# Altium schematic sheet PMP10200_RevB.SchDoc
size 431 x 279 mm; Date: Not shown in title block; ApprovedBy: Not shown in title block; CheckedBy: Not shown in title block; Author: Not shown in title block; CompanyName: Not shown in title block; Engineer: Not shown in title block; Organization: Not shown in title block; Address1: Not shown in title block; Address2: Not shown in title block; Address3: Not shown in title block; Address4: Not shown in title block; DocumentNumber: 1; Revision: Use project parameter SCH_Rev; SheetNumber: 1; SheetTotal: 1; PageSetup: Record=PageOptions¦CenterHorizontal=True¦CenterVertical=True¦PrintScale=1.00¦XCorrection=1.00¦YCorrection=1.00¦PrintKind=0¦BorderSize=5000000¦LeftOffset=0¦BottomOffset=0¦Orientation=2¦PaperLength=1000¦PaperWidth=1000¦Scale=100¦PaperSource=15¦PrintQuality=600¦MediaType=1¦DitherType=10¦PaperKind=Letter¦PrintScaleMode=1
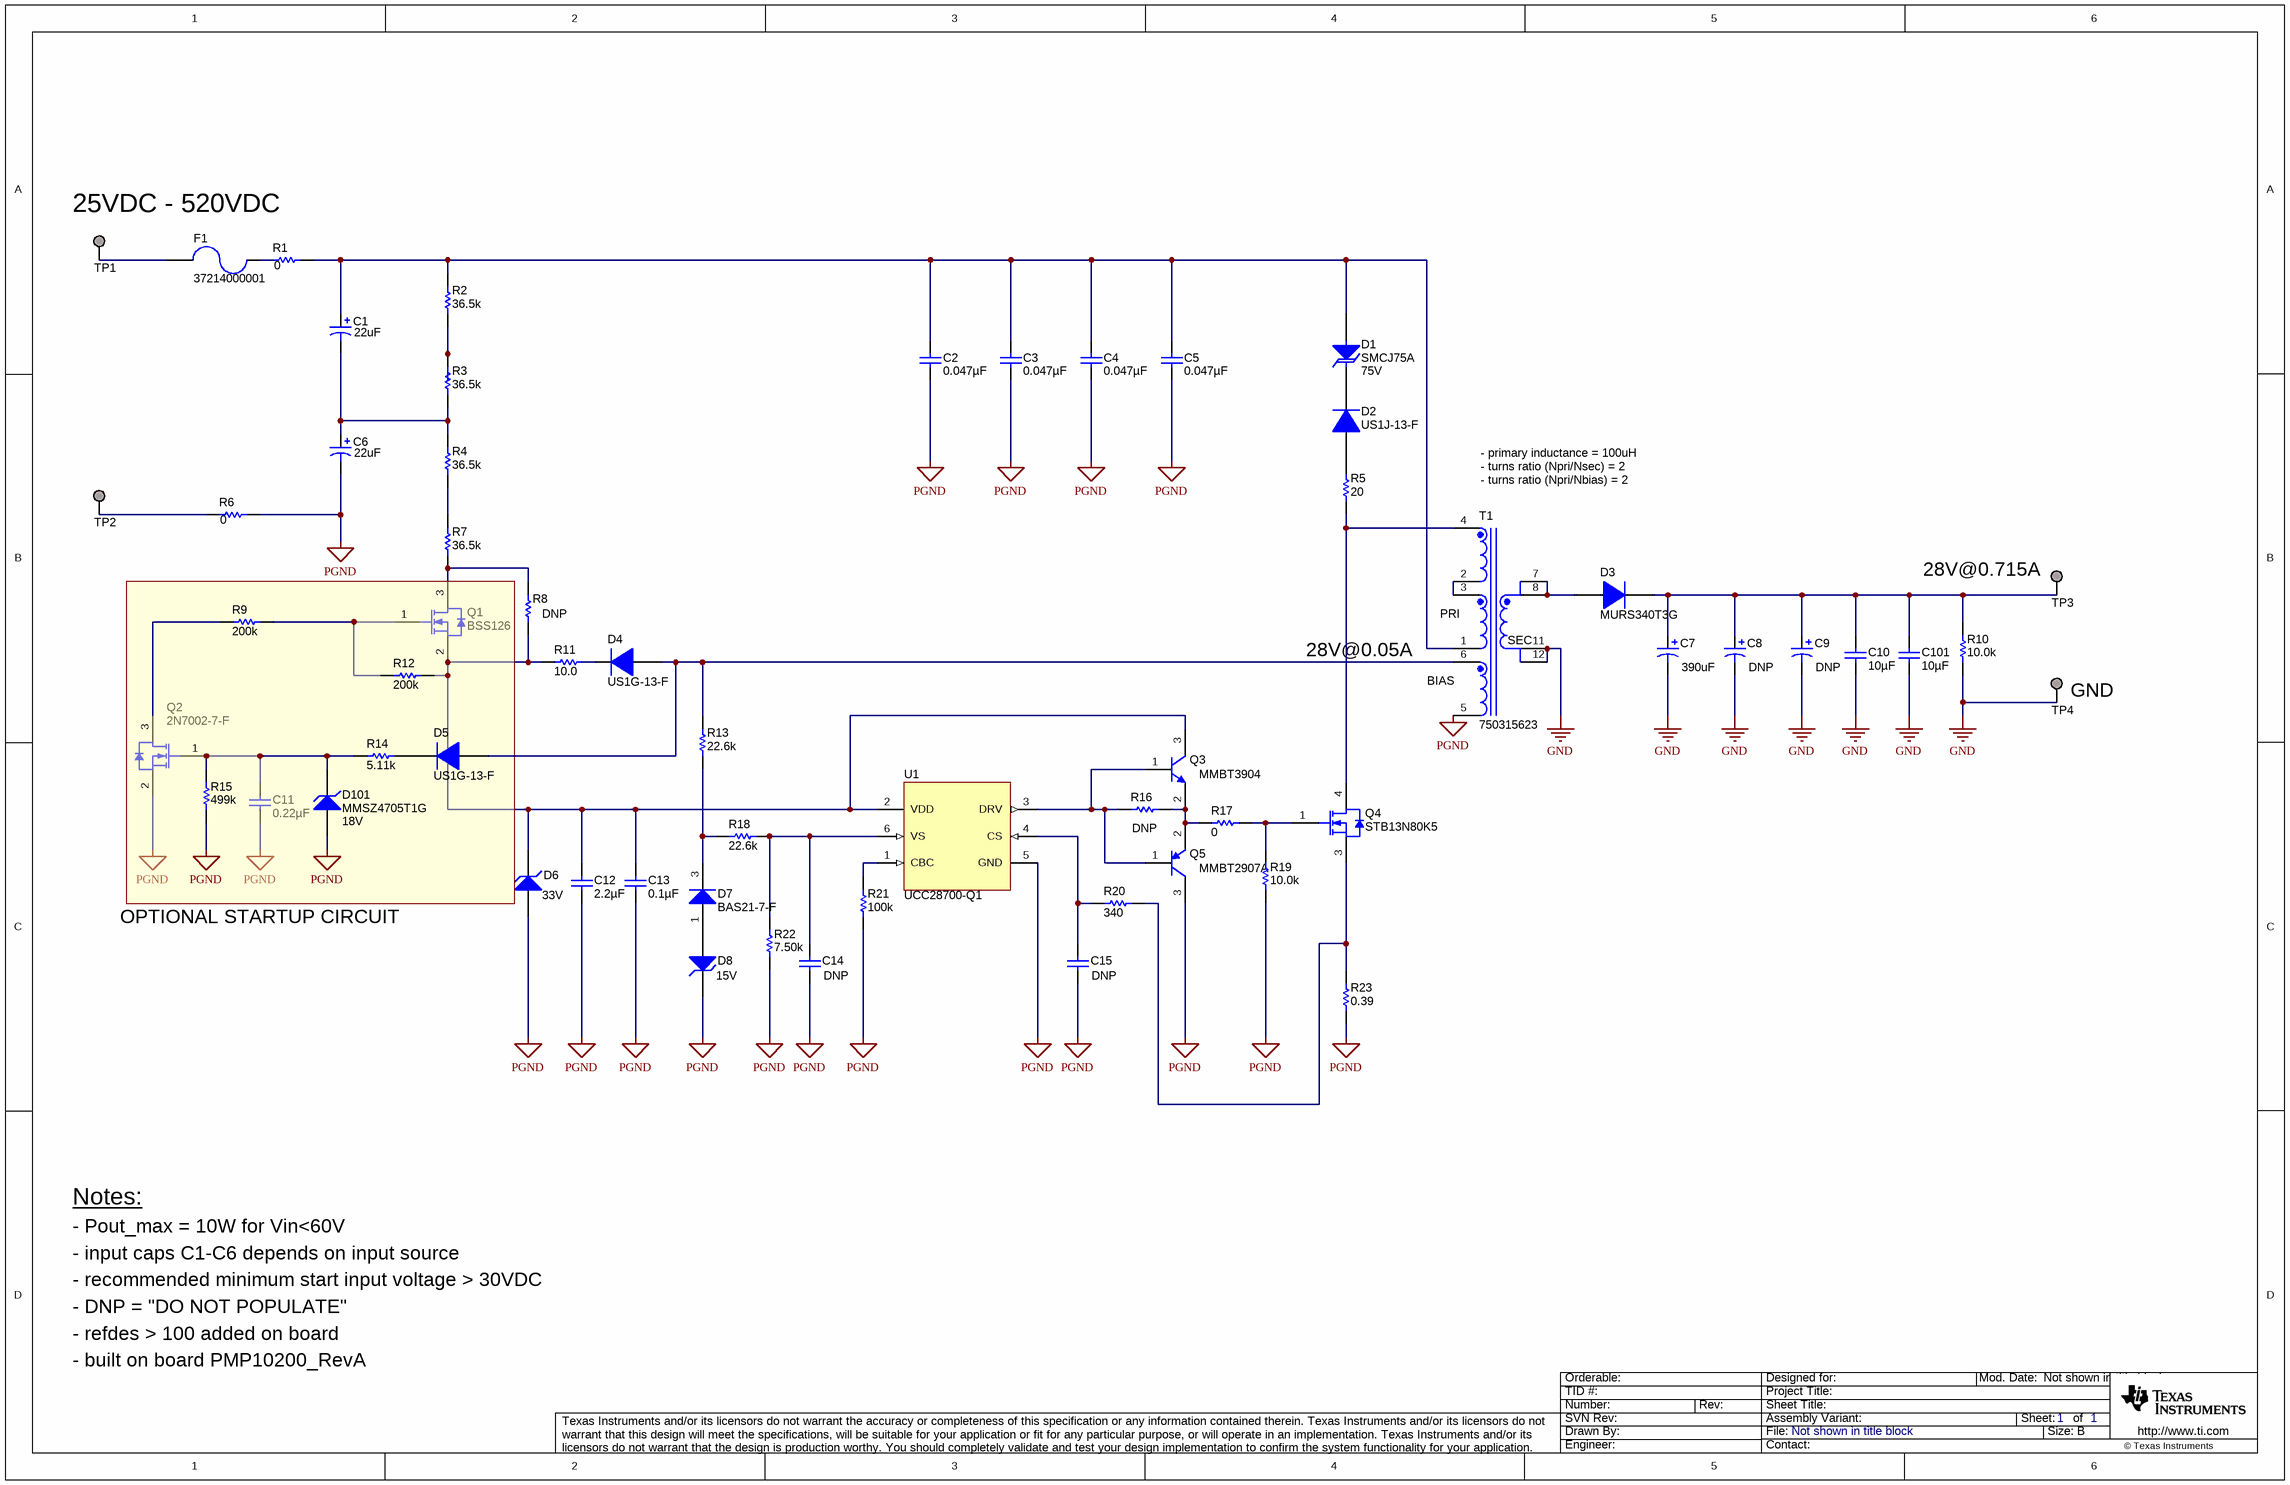
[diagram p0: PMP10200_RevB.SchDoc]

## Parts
C1  value 22uF  [EE_1800x2500]  (hidden comment: EKXG401ELL220)
C2  ValueDisplayed: 0.047µF  [1210]  (hidden comment: GRM32DR72J473KW01L)
C3  ValueDisplayed: 0.047µF  [1210]  (hidden comment: GRM32DR72J473KW01L)
C4  ValueDisplayed: 0.047µF  [1210]  (hidden comment: GRM32DR72J473KW01L)
C5  ValueDisplayed: 0.047µF  [1210]  (hidden comment: GRM32DR72J473KW01L)
C6  value 22uF  [EE_1800x2500]  (hidden comment: EKXG401ELL220)
C7  value 390uF  [SM_RADIAL_J16]  (hidden comment: EEVFK1H391)
C8  DNP  [SM_RADIAL_J16]
C9  value DNP  [SM_RADIAL_J16]  (hidden comment: EEV-FK1H102M)
C10  ValueDisplayed: 10µF  [1210]  (hidden comment: GRM32ER71H106KA12L)
C11  ValueDisplayed: 0.22µF  [0805_HV]  (hidden comment: GRM21BR71H224KA01L)
C12  ValueDisplayed: 2.2µF  [1206_190]  (hidden comment: GCM31CR71H225KA55L)
C13  ValueDisplayed: 0.1µF  [0603]  (hidden comment: C1608X7R1H104K)
C14  DNP  [0603]
C15  DNP  [0603]
C101  ValueDisplayed: 10µF  [1210]  (hidden comment: GRM32ER71H106KA12L)
D1  SMCJ75A  value 75V  [SMC]
D2  US1J-13-F  [SMA]
D3  MURS340T3G  [SMC]
D4  US1G-13-F  [SMA]
D5  US1G-13-F  [SMA]
D6  value 33V  [SOD-123]  (hidden comment: MMSZ5257B-7-F)
D7  BAS21-7-F  [SOT-23]
D8  value 15V  [SMA]  (hidden comment: SMAZ15)
D101  MMSZ4705T1G  value 18V  [SOD-123]
F1  37214000001  [FUSE_372]
Q1  BSS126  [SOT-23]
Q2  2N7002-7-F  [SOT-23]
Q3  MMBT3904  [SOT-23]
Q4  STB13N80K5  [DDPAK]
Q5  MMBT2907A  [SOT-23]
R1  value 0  [1210]  (hidden comment: Used in BOM report)
R2  ValueDisplayed: 36.5k  [1206]  (hidden comment: CRCW120636K5FKEA)
R3  ValueDisplayed: 36.5k  [1206]  (hidden comment: CRCW120636K5FKEA)
R4  ValueDisplayed: 36.5k  [1206]  (hidden comment: CRCW120636K5FKEA)
R5  ValueDisplayed: 20  [2010]  (hidden comment: CRCW201020R0JNEF)
R6  value 0  [1210]  (hidden comment: Used in BOM report)
R7  ValueDisplayed: 36.5k  [1206]  (hidden comment: CRCW120636K5FKEA)
R8  DNP  [0805]
R9  ValueDisplayed: 200k  [0603]  (hidden comment: CRCW0603200KJNEA)
R10  ValueDisplayed: 10.0k  [0805_HV]  (hidden comment: CRCW080510K0FKEA)
R11  ValueDisplayed: 10.0  [0805_HV]  (hidden comment: RC0805FR-0710RL)
R12  ValueDisplayed: 200k  [0603]  (hidden comment: CRCW0603200KJNEA)
R13  ValueDisplayed: 22.6k  [0603]  (hidden comment: CRCW060322K6FKEA)
R14  ValueDisplayed: 5.11k  [0805_HV]  (hidden comment: CRCW08055K11FKEA)
R15  ValueDisplayed: 499k  [0603]  (hidden comment: CRCW0603499KFKEA)
R16  DNP  [0805_HV]
R17  ValueDisplayed: 0  [0805_HV]  (hidden comment: CRCW08050000Z0EA)
R18  ValueDisplayed: 22.6k  [0603]  (hidden comment: CRCW060322K6FKEA)
R19  ValueDisplayed: 10.0k  [0805_HV]  (hidden comment: CRCW080510K0FKEA)
R20  ValueDisplayed: 340  [0603]  (hidden comment: CRCW0603340RFKEA)
R21  ValueDisplayed: 100k  [0603]  (hidden comment: CRCW0603100KFKEA)
R22  ValueDisplayed: 7.50k  [0603]  (hidden comment: CRCW06037K50FKEA)
R23  ValueDisplayed: 0.39  [1206]  (hidden comment: ERJ-8RQFR39V)
T1  750315623  [Wurth_750315623]
TP1  Suggest using a net name here  [Keystone1503-2]  (value not drawn)
TP2  Suggest using a net name here  [Keystone1503-2]  (value not drawn)
TP3  Suggest using a net name here  [Keystone1503-2]  (value not drawn)
TP4  Suggest using a net name here  [Keystone1503-2]  (value not drawn)
U1  UCC28700-Q1  [DBV0006A_N]

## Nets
GND: C7.2(-) C8.2(-) C9.2(-) C10.2 C101.2 R10.1 T1.11 T1.12 TP4.1
PGND: C2.2 C3.2 C4.2 C5.2 C6.2(-) C11.2 C12.2 C13.2 C14.2 C15.2 D6.2(A) D8.1(K) D101.2(A) Q2.2(S) Q5.3(C) R6.2 R15.1 R19.1 R21.1 R22.1 R23.1 T1.5 U1.5(GND)
NetC1_1: C1.1(+) C2.1 C3.1 C4.1 C5.1 D1.2(A) R1.2 R2.2 T1.1
NetC1_2: C1.2(-) C6.1(+) R3.1 R4.2
NetC7_1: C7.1(+) C8.1(+) C9.1(+) C10.1 C101.1 D3.1(K) R10.2 TP3.1
NetC11_1: C11.1 D101.1(K) Q2.1(G) R14.2 R15.2
NetC12_1: C12.1 C13.1 D6.1(K) Q1.2(S) Q3.3(C) R8.1 R11.1 R12.2 U1.2(VDD)
NetC14_1: C14.1 R18.1 R22.2 U1.6(VS)
NetC15_1: C15.1 R20.1 U1.4(CS)
NetD1_1: D1.1(K) D2.1(K)
NetD2_2: D2.2(A) R5.2
NetD3_2: D3.2(A) T1.7 T1.8
NetD4_1: D4.1(K) R11.2
NetD4_2: D4.2(A) D5.2(A) R13.1 T1.6
NetD5_1: D5.1(K) R14.1
NetD7_1: D7.1(A) D8.2(A)
NetD7_3: D7.3(K) R13.2 R18.2
NetF1_1: F1.1 R1.1
NetF1_2: F1.2 TP1.1
NetQ1_1: Q1.1(G) R9.2 R12.1
NetQ1_3: Q1.3(D) R7.1 R8.2
NetQ2_3: Q2.3(D) R9.1
NetQ3_1: Q3.1(B) Q5.1(B) R16.1 U1.3(DRV)
NetQ3_2: Q3.2(E) Q5.2(E) R16.2 R17.1
NetQ4_1: Q4.1(G) R17.2 R19.2
NetQ4_3: Q4.3(S) R20.2 R23.2
NetQ4_4: Q4.4(D) R5.1 T1.4
NetR2_1: R2.1 R3.2
NetR4_1: R4.1 R7.2
NetR6_1: R6.1 TP2.1
NetR21_2: R21.2 U1.1(CBC)
NetT1_2: T1.2 T1.3

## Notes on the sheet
- 25VDC - 520VDC
- - primary inductance = 100uH
- - turns ratio (Npri/Nsec) = 2
- (near T1) - turns ratio (Npri/Nbias) = 2
- (near T1) PRI
- 28V@0.715A
- 28V@0.05A
- (near T1) BIAS
- (near T1) SEC
- (near TP4) GND
- OPTIONAL STARTUP CIRCUIT
- - Pout_max = 10W for Vin<60V
- Notes:
- - recommended minimum start input voltage > 30VDC
- - input caps C1-C6 depends on input source
- - DNP = "DO NOT POPULATE"
- - refdes > 100 added on board
- - built on board PMP10200_RevA

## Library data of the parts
C1 = EEU-EE2G680: CAP, AL; Manufacturer: Panasonic; Polarized: Y; CompType: Capacitor; U/M: EA; Cap_F: 0.000068; Tolerance_%: 20; Value1: Unknown; VDC_V: 400; Value2: 400V; IRMS_A: 1.49; TaMin_C: -25; TaMax_C: 105; Cap_Case: 18x25mm; Lifetime @ Temp.: 10000 Hrs @ 105°C; Ripple Current: 1.8A
C2-C5 = GRM32DR72J473KW01L: CAP, CERM, 0.047 µF, 630 V, +/- 10%, X7R, 1210; Manufacturer: MuRata; Polarized: N; CompType: Capacitor; Value: 0.047uF; U/M: EA; Cap_F: 0.000000047; Tolerance_%: 10; Value1: Unknown; VDC_V: 630; Value2: 630V; TaMin_C: -55; TaMax_C: 125
C6 = EEU-EE2G680: CAP, AL; Manufacturer: Panasonic; Polarized: Y; CompType: Capacitor; ValueDisplayed: 22µF; U/M: EA; Cap_F: 0.000068; Tolerance_%: 20; Value1: Unknown; VDC_V: 400; Value2: 400V; IRMS_A: 1.49; TaMin_C: -25; TaMax_C: 105; Cap_Case: 18x25mm; Lifetime @ Temp.: 10000 Hrs @ 105°C; Ripple Current: 1.8A
C7 = EEV-FK1H102M: CAP, AL, 1000 µF, 50 V, +/- 20%, 0.073 ohm, SMD; Manufacturer: Panasonic; Polarized: Y; CompType: Capacitor; U/M: EA; Cap_F: 0.001; Tolerance_%: 20; VDC_V: 50; Value2: 50V; ESR_ohm: 0.073; IRMS_A: 1.61; TaMin_C: -55; TaMax_C: 105; Cap_Case: J16
C8 C9 = EEV-FK1H102M: CAP, AL, 1000 µF, 50 V, +/- 20%, 0.073 ohm, SMD; Manufacturer: Panasonic; Polarized: Y; CompType: Capacitor; ValueDisplayed: 1000µF; U/M: EA; Cap_F: 0.001; Tolerance_%: 20; VDC_V: 50; Value2: 50V; ESR_ohm: 0.073; IRMS_A: 1.61; TaMin_C: -55; TaMax_C: 105; Cap_Case: J16
C10 C101 = GRM32ER71H106KA12L: CAP, CERM, 10 µF, 50 V, +/- 10%, X7R, 1210; Manufacturer: MuRata; Polarized: N; CompType: Capacitor; Value: 10uF; U/M: EA; Cap_F: 0.00001; Tolerance_%: 10; Value1: Unknown; VDC_V: 50; Value2: 50V; TaMin_C: -55; TaMax_C: 125
C11 = GRM21BR71H224KA01L: CAP, CERM, 0.22 µF, 50 V, +/- 10%, X7R, 0805; Manufacturer: MuRata; Polarized: N; CompType: Capacitor; Value: 0.22uF; U/M: EA; Cap_F: 0.00000022; Tolerance_%: 10; Value1: Unknown; VDC_V: 50; Value2: 50V; TaMin_C: -55; TaMax_C: 125; Cap_Case: 0805
C12 = GCM31CR71H225KA55L: CAP, CERM, 2.2 µF, 50 V, +/- 10%, X7R, 1206_190; Manufacturer: MuRata; Polarized: N; CompType: Capacitor; Value: 2.2uF; U/M: EA; Cap_F: 0.0000022; Tolerance_%: 10; Value1: Unknown; VDC_V: 50; Value2: 50V; TaMin_C: -55; TaMax_C: 125; Cap_Case: 1206
C13 = C1608X7R1H104K: CAP, CERM, 0.1 µF, 50 V, +/- 10%, X7R, 0603; Manufacturer: TDK; Polarized: N; CompType: Capacitor; Value: 0.1uF; U/M: EA; Cap_F: 0.0000001; Tolerance_%: 10; ESR_ohm: 0.017; Value1: 0.017 ohm; VDC_V: 50; Value2: 50V; TaMin_C: -55; TaMax_C: 125
C14 C15 = Capacitor: CAP, CERM, xxxF, xxV, [TempCo], xx%, [PackageReference]; Manufacturer: Used in BOM report; Polarized: N; U/M: EA
D1 = SMCJ75A: Diode, TVS, Uni, 75 V, 1500 W, SMC; Manufacturer: Fairchild Semiconductor; U/M: EA; Power_W: 1500; Vr_V: 75; Value1: 1500W
D2 = US1J-13-F: Diode, Ultrafast, 600 V, 1 A, SMA; Manufacturer: Diodes Inc.; U/M: EA; Vf_V: 1.7; Value: 600V; Value1: 1A; Value2: 1.7V; Io_A: 1; Vr_V: 600; TJmax_C: 150
D3 = MURS340T3G: Diode, Ultrafast, 400 V, 3 A, SMC; Manufacturer: ON Semiconductor; U/M: EA; Vf_V: 1.25; Value: 400V; Value1: 3A; Value2: 1.25V; Io_A: 3; Vr_V: 400; TJmax_C: 175; RJC_CperW: 11
D4 D5 = US1G-13-F: Diode, Ultrafast, 400 V, 1 A, SMA; Manufacturer: Diodes Inc.; U/M: EA; Vf_V: 1.3; Value: 400V; Value1: 1A; Value2: 1.3V; Io_A: 1; Vr_V: 400; TJmax_C: 150
D6 = MMSZ5257B-7-F: Diode, Zener, 33 V, 500 mW, SOD-123; Manufacturer: Diodes Inc.; SymbolCreator: a0412235; U/M: EA; Power_W: 0.5; Vz_V: 33; Value1: 0.5W; RJA_CperW: 350
D7 = BAS21-7-F: Diode, Switching, 200 V, 0.2 A, SOT-23; Manufacturer: Diodes Inc.; U/M: EA; Vf_V: 1.25; Value: 200V; Value1: 0.2A; Value2: 1.25V; Io_A: 0.2; Vr_V: 200; TJmax_C: 150; RJC_CperW: 500
D8 = BZG03C15G: Diode, Zener, 15 V, SMA; Manufacturer: ON Semiconductor; SymbolCreator: a0412235; U/M: EA; Power_W: 1.5; Vz_V: 15; Value1: 1.5W; Tolerance_%: ±5%; Power - Max: 1W; Impedance (Max) (Zzt): 10 Ohm; Current - Reverse Leakage @ Vr: 1µA @ 11.4V
D101 = MMSZ4705T1G: Diode, Zener, 18 V, 500 mW, SOD-123; Manufacturer: ON Semiconductor; SymbolCreator: a0412235; U/M: EA; Power_W: 0.5; Vz_V: 18; Value1: 0.5W; RJA_CperW: 340
F1 = 37214000001: Fuse, 4 A, 250 V, TH; Manufacturer: Littelfuse; U/M: EA; OpeningTime_200%_max: 2; VDC_V: 250; Irating_A: 4; Vdrop: 0.075; Soldering_Wave_MaxTemp_C: 260; Soldering_Wave_MaxTime_s: 5
Q1 = BSS126 H6906: MOSFET, N-CH, 600 V, 0.021 A, SOT-23; Manufacturer: Infineon Technologies; Alternate Manufacturer: None; U/M: EA; ChType: N; Value: 600V; VdsMax_V: 600; Value1: ? ohm; Value2: 1.4 nC; QgTyp_nC: 1.4; Vgs_V: 20; IdsMax_A: 0.021
Q2 = 2N7002-7-F: MOSFET, N-CH, 60 V, 0.17 A, SOT-23; Manufacturer: Diodes Inc.; Alternate Manufacturer: None; U/M: EA; ChType: N; Value: 60V; VdsMax_V: 60; Value1: 7.5 ohm; Rdson45_ohm: 7.5; Value2: 223 nC; QgTyp_nC: 223; Vgs_V: 20; IdsMax_A: 0.17
Q3 = MMBT3904, Fairchild Semiconductor: Transistor, NPN, 40 V, 0.2 A, SOT-23; CompType: BJT; PNP: 0; NPN: 1; Vceo_V: 40; Vcesat1_V: 0.2; Value1: 0.2 A; HfeMax: 300; TaMin_C: -55; TaMax_C: 150; U/M: EA
Q4 = STB11N65M5: MOSFET, N-CH, 800 V, DDPAK; Manufacturer: STMicroelectronics; Alternate Manufacturer: None; U/M: EA; ChType: N; Value: 800V; VdsMax_V: 710; Value1: ? ohm; Value2: 17 nC; QgTyp_nC: 17; Vgs_V: 25; IdsMax_A: 9; FET Type: MOSFET N-Channel, Metal Oxide; FET Feature: Standard; Current - Continuous Drain (Id) @ 25°C: 12A (Tc); Rds On (Max) @ Id, Vgs: 450 mOhm @ 6A, 10V; Vgs(th) (Max) @ Id: 5V @ 100µA; Gate Charge (Qg) @ Vgs: 29nC @ 10V; Input Capacitance (Ciss) @ Vds: 870pF @ 100V; Power - Max: 190W
Q5 = MMBT2907A, Fairchild Semiconductor: Transistor, PNP, 60 V, 0.8 A, SOT-23; CompType: BJT; PNP: 1; NPN: 0; Vceo_V: 60; Vcesat1_V: 1.6; IcRated_A: 0.8; Value1: 0.8 A; HfeMax: 300; TaMin_C: -55; TaMax_C: 150; U/M: EA
R1 R6 = Resistor: RES, xxx ohm, x%, xW, [PackageReference]; U/M: EA
R2-R4 R7 = CRCW120636K5FKEA: RES, 36.5 k, 1%, 0.25 W, 1206; Manufacturer: Vishay-Dale; CompType: Resistor; Value: 36.5k; Res_ohm: 36500; Value_Code: 36k5; Tolerance_%: 1; Power_W: 0.25; Value2: 0.25W; VDC_V: 200; TempCo: 100 ppm/C; EIA_Code: E96; U/M: EA
R5 = CRCW201020R0JNEF: RES, 20, 5%, 0.75 W, 2010; Manufacturer: Vishay-Dale; CompType: Resistor; Value: 20; Value_Code: 20R0; Tolerance_%: 5; Power_W: 0.75; Value2: 0.75W; VDC_V: 400; TempCo: 200 ppm/C; EIA_Code: E24; U/M: EA
R8 = Resistor: RES, xxx ohm, x%, xW, [PackageReference]; Manufacturer: Used in BOM report; U/M: EA
R9 R12 = CRCW0603200KJNEA: RES, 200 k, 5%, 0.1 W, 0603; Manufacturer: Vishay-Dale; CompType: Resistor; Value: 200k; Res_ohm: 200000; Tolerance_%: 5; Power_W: 0.1; Value2: 0.1W; VDC_V: 75; TempCo: 200 ppm/C; EIA_Code: E24; U/M: EA
R10 R19 = CRCW080510K0FKEA: RES, 10.0 k, 1%, 0.125 W, 0805; Manufacturer: Vishay-Dale; CompType: Resistor; Value: 10.0k; Res_ohm: 10000; Value_Code: 10k0; Tolerance_%: 1; Power_W: 0.125; Value2: 0.125W; VDC_V: 150; TempCo: 100 ppm/C; EIA_Code: E96; U/M: EA
R11 = RC0805FR-0710RL: RES, 10.0, 1%, 0.125 W, 0805; Manufacturer: Yageo America; CompType: Resistor; Value: 10.0; Res_ohm: 10; Value_Code: 10R0; Tolerance_%: 1; Power_W: 0.125; Value2: 0.125W; VDC_V: 150; TempCo: 200 ppm/C; EIA_Code: E96; U/M: EA
R13 R18 = CRCW060322K6FKEA: RES, 22.6 k, 1%, 0.1 W, 0603; Manufacturer: Vishay-Dale; CompType: Resistor; Value: 22.6k; Res_ohm: 22600; Value_Code: 22k6; Tolerance_%: 1; Power_W: 0.1; Value2: 0.1W; VDC_V: 75; TempCo: 100 ppm/C; EIA_Code: E96; U/M: EA
R14 = CRCW08055K11FKEA: RES, 5.11 k, 1%, 0.125 W, 0805; Manufacturer: Vishay-Dale; CompType: Resistor; Value: 5.11k; Res_ohm: 5110; Value_Code: 5k11; Tolerance_%: 1; Power_W: 0.125; Value2: 0.125W; VDC_V: 150; TempCo: 100 ppm/C; EIA_Code: E96; U/M: EA
R15 = CRCW0603499KFKEA: RES, 499 k, 1%, 0.1 W, 0603; Manufacturer: Vishay-Dale; CompType: Resistor; Value: 499k; Res_ohm: 499000; Tolerance_%: 1; Power_W: 0.1; Value2: 0.1W; VDC_V: 75; TempCo: 100 ppm/C; EIA_Code: E96; U/M: EA
R16 = CRCW08050000Z0EA: RES, 0, 5%, 0.125 W, 0805; Manufacturer: Vishay-Dale; CompType: Resistor; Res_ohm: 0; Value_Code: 0000; Tolerance_%: 5; Power_W: 0.125; Value2: 0.125W; VDC_V: 150; TempCo: 200 ppm/C; EIA_Code: E24; U/M: EA
R17 = CRCW08050000Z0EA: RES, 0, 5%, 0.125 W, 0805; Manufacturer: Vishay-Dale; CompType: Resistor; Value: 0; Value_Code: 0000; Tolerance_%: 5; Power_W: 0.125; Value2: 0.125W; VDC_V: 150; TempCo: 200 ppm/C; EIA_Code: E24; U/M: EA
R20 = CRCW0603340RFKEA: RES, 340, 1%, 0.1 W, 0603; Manufacturer: Vishay-Dale; CompType: Resistor; Value: 340; Value_Code: 340R; Tolerance_%: 1; Power_W: 0.1; Value2: 0.1W; VDC_V: 75; TempCo: 100 ppm/C; EIA_Code: E96; U/M: EA
R21 = CRCW0603100KFKEA: RES, 100 k, 1%, 0.1 W, 0603; Manufacturer: Vishay-Dale; CompType: Resistor; Value: 100k; Res_ohm: 100000; Tolerance_%: 1; Power_W: 0.1; Value2: 0.1W; VDC_V: 75; TempCo: 100 ppm/C; EIA_Code: E96; U/M: EA
R22 = CRCW06037K50FKEA: RES, 7.50 k, 1%, 0.1 W, 0603; Manufacturer: Vishay-Dale; CompType: Resistor; Value: 7.50k; Res_ohm: 7500; Value_Code: 7k50; Tolerance_%: 1; Power_W: 0.1; Value2: 0.1W; VDC_V: 75; TempCo: 100 ppm/C; EIA_Code: E96; U/M: EA
R23 = ERJ-8RQFR39V: RES, 0.39, 1%, 0.25 W, 1206; Manufacturer: Panasonic; CompType: Resistor; Value: 0.39; Value_Code: R390; Tolerance_%: 1; Power_W: 0.25; Value2: 0.25W; TempCo: 250 ppm/C; EIA_Code: E96; U/M: EA
T1 = 750315623: Transformer, 100 uH, SMT; Manufacturer: Wurth Elektronik; SymbolCreator: Altium; DCR_Ohm: 0.11; Value: 100 uH; U/M: EA
TP1-TP4 = 1503-2: Terminal, Turret, TH, Double; Manufacturer: Keystone; CompType: Turret Terminal; U/M: EA
U1 = UCC28700DBVR: Constant-Voltage, Constant-Current Controller With Primary-Side Regulation, DBV0006A; Alternate PartNumber: UCC28700DBVT; Manufacturer: Texas Instruments; SymbolCreator: a0799628; CompType: IC; U/M: EA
